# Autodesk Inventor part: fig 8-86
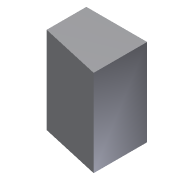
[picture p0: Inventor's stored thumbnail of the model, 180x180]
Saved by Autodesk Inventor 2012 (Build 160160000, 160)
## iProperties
Created: 2009-04
Part Number: fig 8-86
Document SubType Name: Modeling
Designer: Sham
Density: 1 g/cm^3
Material: Default
Author: Sham
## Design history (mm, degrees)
sketch "Sketch5"
  geometry: L1 (14, -20)-(0, -20); L2 (0, -20)-(0, 0); L3 (0, 0)-(14, 0); L4 (14, 0)-(14, -20)
  constraints: 8 end point
extrude "Extrusion2" new body sketch "Sketch5" distance "d3" = 20; taper "d4" = 0 deg
sketch "Sketch6"
  geometry: L1 (-5, 12)-(17, 7)
  constraints: 2 end point
split "Split8" sketch "Sketch6"
body "Solid2"
